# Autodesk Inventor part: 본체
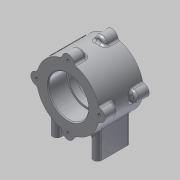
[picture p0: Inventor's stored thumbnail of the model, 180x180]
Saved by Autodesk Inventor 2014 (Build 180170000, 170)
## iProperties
Created: 2015-03
Part Number: 본체
Material: 알루미늄 6061
Document SubType Name: Modeling
Designer: MYHOME
Mass: 450.761 g
Surface Area: 333.126 cm^2
Volume: 166.332 cm^3
Density: 2.71 g/cm^3
Appearance: 알루미늄 - 평지
Author: MYHOME
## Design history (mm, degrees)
sketch "스케치2"
  geometry: C1 r 37 at (0, 56); 1 further point
  constraints: 1 centre point, 1 vertical alignment
  dimensions: "d0" = 74 diameter of C1; "d1" = 56 distance of point (0, 0) C1.centre
extrude "돌출1" new body sketch "스케치2" stored distance "d2" = 52; taper "d3" = 0 deg
sketch "스케치3"
  geometry: C1 r 7 at (0, 37); C2 r 7 at (37, 0); C3 r 7 at (0, -37); C4 r 7 at (-37, 0); A1 r 37 centre (0, 0) between (0, 37) and (37, 0) reference; 1 further point
  constraints: 4 centre point, 4 point on circle, 2 horizontal alignment, 2 vertical alignment
  dimensions: "d4" = 7 radius of C1; "d5" = 7 radius of C2; "d6" = 7 radius of C3; "d7" = 7 radius of C4
extrude "돌출2" join sketch "스케치3" distance "d8" = 15; taper "d9" = 0 deg
hole "구멍1" diameter "d12" = 42; stored, may be unused: countersink angle "d16" = 90 deg, drill point angle "d18" = 0 deg; dims "d10" = 10, "d11" = 10, "d13" = 6, "d14" = 47, "d15" = 22, "d17" = 8
sketch "스케치4"
  geometry: A1 r 7 centre (0, 19) between (-6.969, 19.662) and (6.969, 19.662) reference; A2 r 7 centre (37, 56) between (36.338, 49.031) and (36.338, 62.969) reference; A3 r 7 centre (0, 93) between (6.969, 92.338) and (-6.969, 92.338) reference; A4 r 7 centre (-37, 56) between (-36.338, 62.969) and (-36.338, 49.031) reference; 5 further points
  constraints: 4 coincident
hole "구멍2" sketch "스케치4" at (-37, 56), (0, 93), (37, 56), (0, 19) diameter "d19" = 3.242; stored, may be unused: countersink angle "d23" = 90 deg, drill point angle "d25" = 118 deg; dims "d20" = 8, "d21" = 47, "d22" = 22, "d24" = 11
chamfer "모따기1" distance "d26" = 1; stored, may be unused: second distance "d27" = 2, angle "d28" = 45 deg
sketch "스케치5"
  geometry: C1 r 21 at (0, -56) reference; C2 r 23.5 at (0, -56); 1 further point
  constraints: 1 centre point, 1 coincident
  dimensions: "d29" = 47 diameter of C2
extrude "돌출3" cut sketch "스케치5" distance "d30" = 22; taper "d31" = 0 deg
chamfer "모따기2" distance "d32" = 1; stored, may be unused: second distance "d33" = 2, angle "d34" = 45 deg
sketch "스케치6"
  geometry: L1 (-24, 15)-(-24, -15); L2 (-29, 15)-(-29, -15); L3 (-19, -15)-(-19, 15); L4 (24, 15)-(24, -15); L5 (19, 15)-(19, -15); L6 (29, -15)-(29, 15); A1 r 5 centre (-24, 15) between (-19, 15) and (-29, 15); A2 r 5 centre (-24, -15) between (-29, -15) and (-19, -15); A3 r 5 centre (24, 15) between (29, 15) and (19, 15); A4 r 5 centre (24, -15) between (19, -15) and (29, -15); 3 further points
  constraints: 16 end point, 8 point on circle, 8 tangent, 4 centre point, 4 parallel, 2 horizontal alignment, 2 midpoint, 1 equal radius, 1 vertical
  dimensions: "d35" = 40 dimension on A3 A4; "d36" = 5 radius of A3; "d37" = 48 distance of L1.end L4.end; "d38" = 24 distance of point (24, 0) point (0, 0)
extrude "돌출4" join sketch "스케치6" stored distance "d39" = 22; taper "d40" = 0 deg
sketch "스케치7"
  geometry: L1 (-19, 15)-(-19, -15) reference; L2 (-29, -15)-(-29, 15) reference; A1 r 5 centre (24, 15) between (29, 15) and (19, 15) reference; A2 r 5 centre (24, -15) between (19, -15) and (29, -15) reference; A3 r 5 centre (-24, 15) between (-19, 15) and (-29, 15) reference; A4 r 5 centre (-24, -15) between (-29, -15) and (-19, -15) reference; 5 further points
  constraints: 4 coincident
hole "구멍3" sketch "스케치7" at (-24, 15), (-24, -15), (24, -15), (24, 15) diameter "d41" = 4.134; stored, may be unused: countersink angle "d45" = 90 deg, drill point angle "d47" = 118 deg; dims "d42" = 6, "d43" = 47, "d44" = 22, "d46" = 8
fillet "모깎기1" dims "d48" = 3
fillet "모깎기2" dims "d49" = 3
fillet "모깎기3" dims "d50" = 3
sketch "스케치8"
  geometry: L1 (0, 56)-(0, 93); L2 (0, 56)-(26.163, 82.163); C1 r 1.621 at (0, 19) reference; C2 r 1.621 at (0, 93) reference; C3 r 1.621 at (37, 56) reference; C4 r 1.621 at (-37, 56) reference; C5 r 24.5 at (0, 56) reference; A1 r 37 centre (0, 56) between (35.863, 65.104) and (9.104, 91.863) reference; A2 r 3 centre (9.842, 94.77) between (6.889, 94.239) and (9.104, 91.863) reference; A3 r 7 centre (0, 93) between (6.889, 94.239) and (-6.889, 94.239) reference; A4 r 3 centre (-9.842, 94.77) between (-9.104, 91.863) and (-6.889, 94.239) reference; A5 r 37 centre (0, 56) between (-9.104, 91.863) and (-35.863, 65.104) reference; A6 r 3 centre (-38.77, 65.842) between (-38.239, 62.889) and (-35.863, 65.104) reference; A7 r 7 centre (-37, 56) between (-38.239, 62.889) and (-38.239, 49.111) reference; A8 r 3 centre (-38.77, 46.158) between (-35.863, 46.896) and (-38.239, 49.111) reference; A9 r 37 centre (0, 56) between (-35.863, 46.896) and (-9.104, 20.138) reference; A10 r 3 centre (-9.842, 17.23) between (-6.889, 17.761) and (-9.104, 20.138) reference; A11 r 7 centre (0, 19) between (-6.889, 17.761) and (6.889, 17.761) reference; A12 r 3 centre (9.842, 17.23) between (9.104, 20.138) and (6.889, 17.761) reference; A13 r 37 centre (0, 56) between (9.104, 20.138) and (35.863, 46.896) reference; A14 r 3 centre (38.77, 46.158) between (38.239, 49.111) and (35.863, 46.896) reference; A15 r 7 centre (37, 56) between (38.239, 49.111) and (38.239, 62.889) reference; A16 r 3 centre (38.77, 65.842) between (35.863, 65.104) and (38.239, 62.889) reference; 2 further points
  constraints: 4 end point, 1 coincident, 1 point on circle, 1 vertical
  dimensions: "d51" = 45 deg angle of L1 L2
  node "투영된 루프2"
node "작업 평면2"
  node "작업 평면1"
sketch "스케치9"
  geometry: L1 (-26, 18.921)-(-26, -18.921) reference; 4 further points
  constraints: 2 coincident, 1 other
  dimensions: "d55" = 26 distance from line of L1 point (0, 0)
feature "엠보싱1" sketch "스케치9" dims "d53" = 0.5, "d54" = 0
node "솔리드1"
mirror "대칭1"
node "투영된 루프1"
other parameters: "d52" = 0.5
